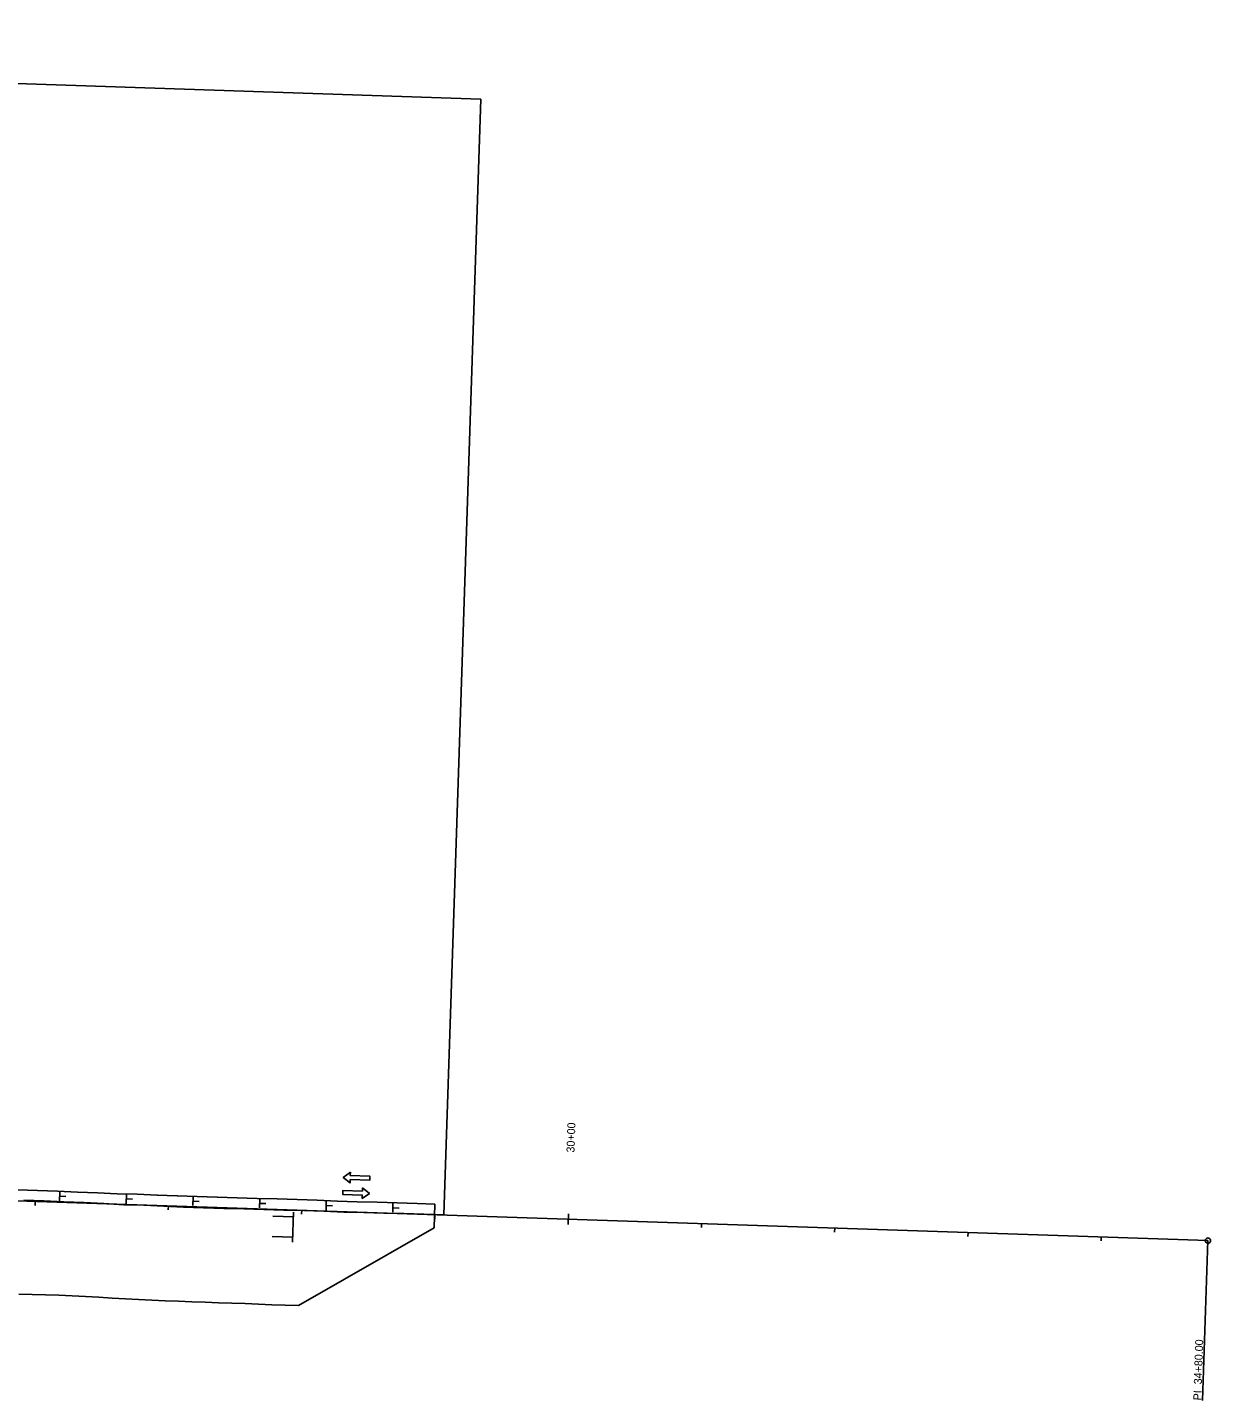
# Model space of a CAD drawing. Extents: x 976309 to 984300, y 1525948 to 1527339.
# Drawn here: x 978543 to 979430, y 1526309 to 1527339 of the extents above; entities that cross this region are included whole.
import ezdxf

# ---------------------------------------------------------------- set-up
doc = ezdxf.new("R2010")
doc.units = 0
for name, color, linetype in [('R_Draft', 7, 'Continuous'), ('R_Horz Alg', 7, 'Continuous'), ('R_Horz Alg Annot', 7, 'Continuous'), ('R_MOT', 7, 'Continuous'), ('R_No Plot', 7, 'Continuous'), ('R_Striping', 7, 'Continuous')]:
    doc.layers.add(name, color=color, linetype=linetype)

msp = doc.modelspace()

# ---------------------------------------------------------------- linework, layer by layer
at = {"layer": 'R_Draft'}
for p, q in [((978847.9, 1526438.7), (978848.5, 1526456.3)), ((978746.2, 1526380.3), (978847.9, 1526438.7))]:
    msp.add_line(p, q, dxfattribs=at)
for points in [[(978848.5, 1526456.3), (978835.2, 1526456.8), (978820.2, 1526457.3), (978805.2, 1526457.8), (978790.2, 1526458.2), (978775.2, 1526458.7), (978775.2, 1526458.7), (978760.2, 1526459.3), (978745.2, 1526459.8), (978745.2, 1526459.8), (978730.2, 1526460.3), (978730.2, 1526460.3), (978715.2, 1526460.7), (978700.2, 1526461.2), (978685.2, 1526461.7), (978685.2, 1526461.7), (978670.2, 1526462.2), (978655.2, 1526462.7), (978655.2, 1526462.7), (978640.2, 1526463.2), (978640.2, 1526463.2), (978625.2, 1526463.8), (978625.2, 1526463.8), (978610.2, 1526464.2), (978595.3, 1526464.8), (978580.3, 1526465.5), (978565.3, 1526466.1), (978550.3, 1526466.6), (978535.3, 1526467.2)], [(978536.3, 1526389), (978546.3, 1526388.7), (978556.3, 1526388.4), (978566.3, 1526388.1), (978576.3, 1526387.7), (978586.3, 1526387.2), (978596.3, 1526386.6), (978606.3, 1526386), (978616.3, 1526385.4), (978626.2, 1526384.8), (978636.2, 1526384.4), (978646.2, 1526384), (978656.2, 1526383.6), (978666.2, 1526383.2), (978676.2, 1526382.9), (978686.2, 1526382.5), (978696.2, 1526382.2), (978706.2, 1526381.8), (978716.2, 1526381.4), (978726.2, 1526381), (978736.2, 1526380.7), (978746.2, 1526380.3)]]:
    msp.add_lwpolyline(points, dxfattribs=at)
at = {"layer": 'R_Horz Alg'}
msp.add_line((976649.7, 1526522), (979428.2, 1526429.1), dxfattribs=at)
at = {"layer": 'R_Horz Alg Annot'}
for points in [[(978548.6, 1526455.5), (978548.7, 1526458.5)], [(978648.5, 1526452.2), (978648.6, 1526455.2)], [(978748.5, 1526448.8), (978748.6, 1526451.8)], [(978848.4, 1526445.5), (978848.5, 1526448.5)], [(978948.6, 1526449.1), (978948.3, 1526441.1)], [(979048.3, 1526438.8), (979048.4, 1526441.8)], [(979148.2, 1526435.5), (979148.3, 1526438.5)], [(979248.2, 1526432.1), (979248.3, 1526435.1)], [(979348.1, 1526428.8), (979348.2, 1526431.8)], [(979428.2, 1526429.1), (979424.2, 1526309.2)]]:
    msp.add_lwpolyline(points, dxfattribs=at)
msp.add_circle((979428.2, 1526429.1), 2, dxfattribs=at)
at = {"layer": 'R_MOT'}
for p, q in [((978566.9, 1526458.9), (978567.2, 1526465.7)), ((978567.1, 1526462.3), (978571.7, 1526462.1)), ((978616.9, 1526457), (978617.1, 1526463.7)), ((978617.1, 1526460.3), (978621.7, 1526460.2)), ((978666.9, 1526455.3), (978667.1, 1526462)), ((978667.1, 1526458.6), (978671.7, 1526458.5)), ((978716.9, 1526453.6), (978717.1, 1526460.4)), ((978717.1, 1526457), (978721.7, 1526456.9)), ((978766.8, 1526452), (978767, 1526458.7)), ((978767, 1526455.4), (978771.6, 1526455.2)), ((978816.8, 1526450.3), (978817, 1526457.1)), ((978726.9, 1526447.4), (978742.3, 1526446.9)), ((978741.6, 1526427.9), (978742.4, 1526450.4)), ((978817, 1526453.7), (978821.6, 1526453.5)), ((978726.4, 1526432.2), (978741.8, 1526431.7))]:
    msp.add_line(p, q, dxfattribs=at)
at = {"layer": 'R_No Plot'}
for p, q in [((977271.9, 1527338.5), (978883, 1527284.8)), ((978883, 1527284.8), (978855.1, 1526448.5))]:
    msp.add_line(p, q, dxfattribs=at)
msp.add_lwpolyline([(978855.1, 1526448.5), (978840.1, 1526449), (978825.1, 1526449.4), (978810.1, 1526449.6), (978795.1, 1526450.1), (978780.1, 1526450.5), (978765.1, 1526451.1), (978750.1, 1526451.6), (978735.1, 1526452), (978720.1, 1526452.4), (978705.1, 1526452.9), (978690.1, 1526453.2), (978675, 1526453.7), (978660, 1526454.1), (978645.1, 1526454.9), (978630.1, 1526455.6), (978615.1, 1526456), (978600.1, 1526457), (978585.1, 1526457.7), (978570.2, 1526458.2), (978555.2, 1526458.8), (978540.2, 1526459.3)], dxfattribs=at)
at = {"layer": 'R_Striping'}
for points in [[(978785.1, 1526480.3), (978779.7, 1526476.4), (978784.8, 1526472.3), (978784.9, 1526474.8), (978799.6, 1526474.3), (978799.7, 1526477.3), (978785, 1526477.8)], [(978794.2, 1526468.7), (978799.3, 1526464.5), (978793.9, 1526460.7), (978794, 1526463.2), (978779.3, 1526463.7), (978779.4, 1526466.7), (978794.1, 1526466.2)]]:
    msp.add_lwpolyline(points, close=True, dxfattribs=at)

# ---------------------------------------------------------------- texts
at = {"layer": 'R_Horz Alg Annot'}
for s, p in [('30+00', (978953.1, 1526495)), ('PI  34+80.00', (979423.2, 1526309.2))]:
    msp.add_text(s, height=6, rotation=88.0852, dxfattribs=at).set_placement(p)

doc.saveas('drawing.dxf')
